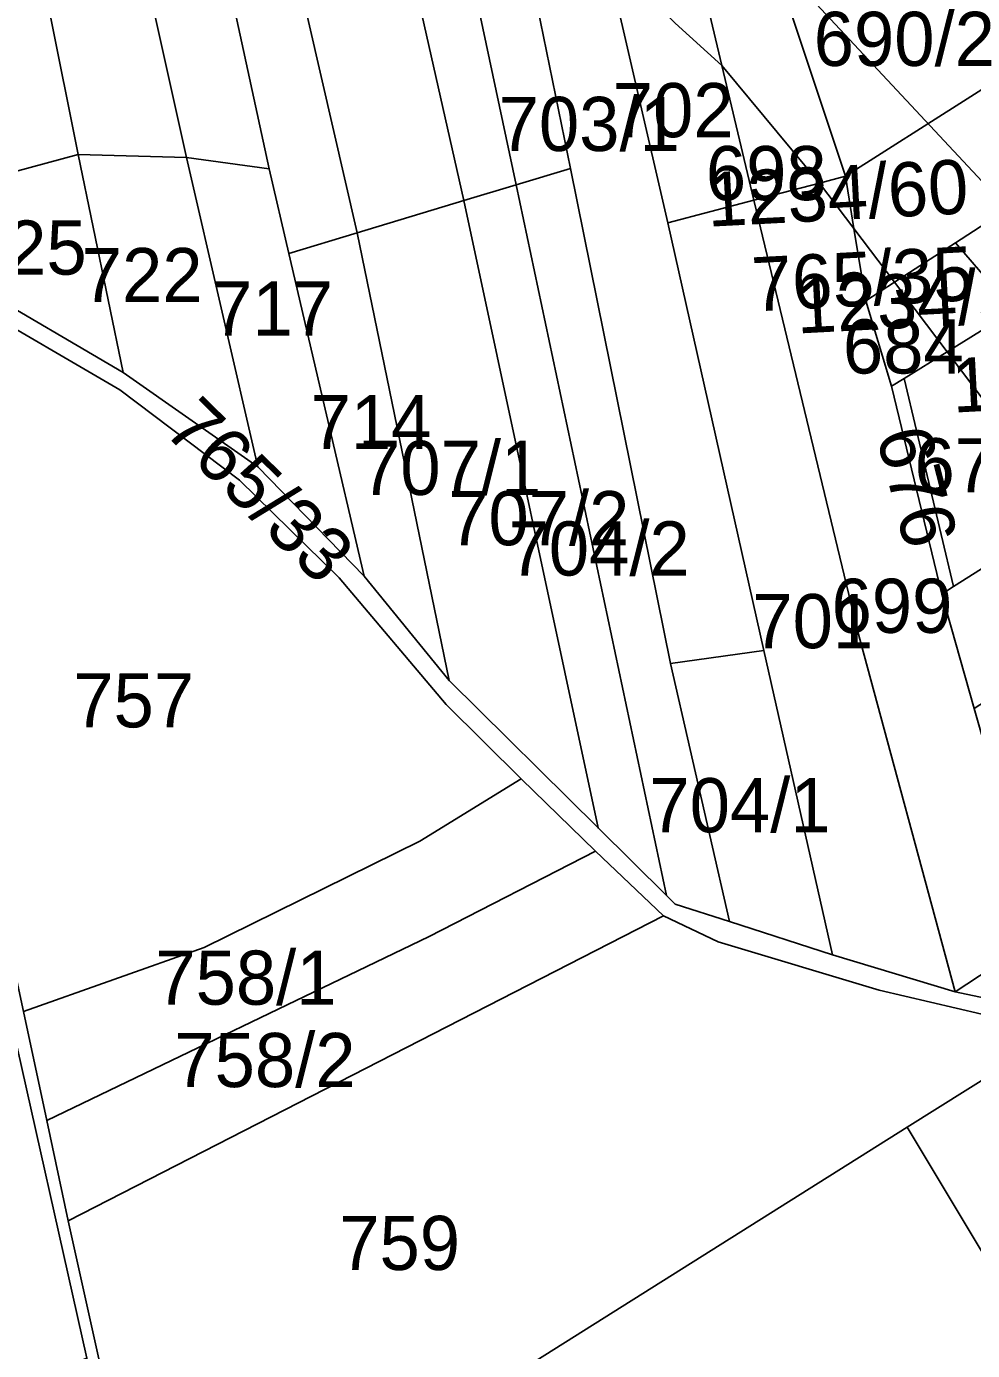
# Model space of a CAD drawing. Extents: x -623250 to -619626, y -1079612 to -1075424.
# Drawn here: x -620640.4 to -620465.7, y -1076980.5 to -1076735.9 of the extents above; entities that cross this region are included whole.
import ezdxf

# ---------------------------------------------------------------- set-up
doc = ezdxf.new("R2010")
doc.units = 0
for name, color, linetype in [('Dálnice a přivaděč', 7, 'Continuous'), ('Parcela nároku', 7, 'Continuous'), ('Parcelní číslo', 7, 'Continuous')]:
    doc.layers.add(name, color=color, linetype=linetype)

msp = doc.modelspace()

# ---------------------------------------------------------------- linework, layer by layer
at = {"layer": 'Dálnice a přivaděč'}
msp.add_lwpolyline([(-621211.3, -1075762.42), (-621042.48, -1076053.84), (-620715.11, -1076495.7), (-620421.91, -1076809.46), (-620180.94, -1077181.74)], dxfattribs=at)
at = {"layer": 'Parcela nároku'}
for points in [[(-620543.35, -1076610.93), (-620536.54, -1076607.9), (-620532.42, -1076606.06), (-620514.1, -1076675.6), (-620499.51, -1076732.52), (-620489.18, -1076763.57), (-620493.96, -1076764.83), (-620511.99, -1076743.12)], [(-620511.99, -1076743.12), (-620543.35, -1076610.93), (-620557.72, -1076617.33), (-620533.39, -1076722.78), (-620520.6, -1076735.3)], [(-620635.93, -1076647.3), (-620621.75, -1076641.56), (-620595.61, -1076762.2), (-620610.84, -1076760.14)], [(-620579.37, -1076774.02), (-620608.07, -1076649.13), (-620615.95, -1076642.08), (-620621.75, -1076641.56), (-620595.61, -1076762.2), (-620591.96, -1076777.82)], [(-620652.12, -1076653.85), (-620635.93, -1076647.3), (-620610.84, -1076760.14), (-620630.85, -1076759.56)], [(-620602.88, -1076653.77), (-620608.07, -1076649.13), (-620579.37, -1076774.02), (-620559.63, -1076768.06), (-620579.88, -1076678.27), (-620594.27, -1076664.58)], [(-620630.85, -1076759.56), (-620652.12, -1076653.85), (-620672.93, -1076659.55), (-620653.89, -1076765.75)], [(-620565.57, -1076691.88), (-620549.99, -1076765.15), (-620559.63, -1076768.06), (-620579.88, -1076678.27)], [(-620551.56, -1076705.2), (-620565.57, -1076691.88), (-620549.99, -1076765.15), (-620539.97, -1076762.12)], [(-620521.99, -1076772.19), (-620533.39, -1076722.78), (-620543.71, -1076712.67), (-620551.56, -1076705.2), (-620539.97, -1076762.12), (-620521.46, -1076853.55), (-620504.22, -1076851.17)], [(-620444.22, -1076735), (-620463.25, -1076710), (-620499.51, -1076732.52), (-620489.18, -1076763.57)], [(-620506.08, -1076768.01), (-620511.99, -1076743.12), (-620520.6, -1076735.3), (-620533.39, -1076722.78), (-620521.99, -1076772.19)], [(-620426.15, -1076723.52), (-620413.32, -1076739.86), (-620427.55, -1076749.09), (-620468.83, -1076775.85), (-620480.1, -1076783.16), (-620487.6, -1076773.24), (-620489.18, -1076763.57), (-620444.22, -1076735)], [(-620493.96, -1076764.83), (-620511.99, -1076743.12), (-620506.08, -1076768.01)], [(-620468.83, -1076775.85), (-620427.55, -1076749.09), (-620395.97, -1076793.06), (-620447.85, -1076825.87), (-620470.39, -1076795.99), (-620458.1, -1076788.35)], [(-620630.85, -1076759.56), (-620653.89, -1076765.75), (-620649.92, -1076783.79), (-620622.54, -1076799.85)], [(-620630.85, -1076759.56), (-620610.84, -1076760.14), (-620597.67, -1076817.24), (-620622.54, -1076799.85)], [(-620595.61, -1076762.2), (-620591.96, -1076777.82), (-620578.04, -1076837.42), (-620597.67, -1076817.24), (-620610.84, -1076760.14)], [(-620539.97, -1076762.12), (-620549.99, -1076765.15), (-620522.22, -1076896.42), (-620520.62, -1076898), (-620510.61, -1076901.23), (-620521.46, -1076853.55)], [(-620549.99, -1076765.15), (-620522.22, -1076896.42), (-620534.86, -1076883.93), (-620559.63, -1076768.06)], [(-620459.26, -1076883.5), (-620465.39, -1076861.89), (-620471.39, -1076840.75), (-620480.64, -1076802.35), (-620485.41, -1076786.6), (-620487.6, -1076773.24), (-620493.96, -1076764.83), (-620506.08, -1076768.01), (-620486.96, -1076847.48), (-620468.89, -1076914.21), (-620453.43, -1076904.03)], [(-620489.18, -1076763.57), (-620487.6, -1076773.24), (-620493.96, -1076764.83)], [(-620559.63, -1076768.06), (-620579.37, -1076774.02), (-620562.37, -1076856.73), (-620534.86, -1076883.93)], [(-620486.96, -1076847.48), (-620506.08, -1076768.01), (-620521.99, -1076772.19), (-620504.22, -1076851.17), (-620491.57, -1076907.38), (-620468.89, -1076914.21)], [(-620480.1, -1076783.16), (-620487.6, -1076773.24), (-620485.41, -1076786.6)], [(-620579.37, -1076774.02), (-620591.96, -1076777.82), (-620578.04, -1076837.42), (-620562.37, -1076856.73)], [(-620480.1, -1076783.16), (-620468.83, -1076775.85), (-620458.1, -1076788.35), (-620470.39, -1076795.99)], [(-620623.15, -1076803.02), (-620601.05, -1076819.72), (-620582.67, -1076837.73), (-620562.89, -1076861.13), (-620549.06, -1076874.88), (-620567.8, -1076886.37), (-620607.58, -1076906.02), (-620640.94, -1076917.83), (-620670.91, -1076778.68), (-620669.62, -1076778.45), (-620650.89, -1076786.88)], [(-620470.39, -1076795.99), (-620480.1, -1076783.16), (-620485.41, -1076786.6), (-620480.64, -1076802.35), (-620478.32, -1076800.91)], [(-620478.32, -1076800.91), (-620470.39, -1076795.99), (-620447.85, -1076825.87), (-620469.2, -1076839.37)], [(-620480.64, -1076802.35), (-620478.32, -1076800.91), (-620469.2, -1076839.37), (-620471.39, -1076840.75)], [(-620471.39, -1076840.75), (-620469.2, -1076839.37), (-620447.85, -1076825.87), (-620435.51, -1076842.53), (-620465.39, -1076861.89)], [(-620521.46, -1076853.55), (-620504.22, -1076851.17), (-620491.57, -1076907.38), (-620510.61, -1076901.23)], [(-620607.58, -1076906.02), (-620640.94, -1076917.83), (-620636.67, -1076937.95), (-620566.06, -1076904), (-620535.32, -1076888.25), (-620549.06, -1076874.88), (-620567.8, -1076886.37)], [(-620468.89, -1076914.21), (-620453.43, -1076904.03), (-620410.62, -1076875.82), (-620409.48, -1076880.02), (-620402.02, -1076890.65), (-620445.03, -1076919.25)], [(-620566.06, -1076904), (-620535.32, -1076888.25), (-620522.79, -1076900.14), (-620632.74, -1076956.48), (-620636.67, -1076937.95)], [(-620512.67, -1076904.97), (-620482.96, -1076913.88), (-620449.74, -1076921.67), (-620477.8, -1076939.19), (-620617.09, -1077026.85), (-620632.74, -1076956.48), (-620522.79, -1076900.14)], [(-620629.28, -1076981.86), (-620643.85, -1076916.74), (-620738.29, -1076956.01), (-620832.54, -1076995.23), (-620921.02, -1077031.86), (-620904.58, -1077095.56), (-620767.08, -1077038.8)], [(-620427.21, -1076931.7), (-620396.89, -1076943.7), (-620453.59, -1076979.51), (-620477.8, -1076939.19), (-620449.74, -1076921.67)], [(-620617.09, -1077026.85), (-620477.8, -1076939.19), (-620453.59, -1076979.51), (-620607.45, -1077074.44)]]:
    msp.add_lwpolyline(points, close=True, dxfattribs=at)
for points in [[(-620445.03, -1076919.25), (-620468.89, -1076914.21), (-620491.57, -1076907.38), (-620510.61, -1076901.23), (-620520.62, -1076898), (-620522.22, -1076896.42), (-620534.86, -1076883.93), (-620562.37, -1076856.73), (-620578.04, -1076837.42), (-620597.67, -1076817.24), (-620622.54, -1076799.85), (-620649.92, -1076783.79)], [(-620650.89, -1076786.88), (-620623.15, -1076803.02), (-620601.05, -1076819.72), (-620582.67, -1076837.73), (-620562.89, -1076861.13), (-620549.06, -1076874.88), (-620535.32, -1076888.25), (-620522.79, -1076900.14), (-620512.67, -1076904.97), (-620482.96, -1076913.88), (-620449.74, -1076921.67)], [(-620564.8, -1077306.77), (-620573.82, -1077257.79), (-620578.2, -1077237.62), (-620588.31, -1077189.72), (-620593.55, -1077165.29), (-620597.96, -1077153.14), (-620599.73, -1077148.14), (-620603.79, -1077103.85), (-620607.96, -1077083.92), (-620610.74, -1077070.63), (-620615.34, -1077048.34), (-620618.82, -1077032.03), (-620624.13, -1077006.64), (-620629.28, -1076981.86), (-620643.85, -1076916.74)], [(-620640.94, -1076917.83), (-620636.67, -1076937.95), (-620632.74, -1076956.48), (-620617.09, -1077026.85), (-620607.45, -1077074.44), (-620600.78, -1077101.61), (-620599.35, -1077114.69), (-620595.04, -1077151.27), (-620591.05, -1077163.8), (-620588.33, -1077176.95), (-620585.6, -1077190.18), (-620579.59, -1077219.23), (-620577.16, -1077230.36), (-620574.34, -1077243.71), (-620571.27, -1077258.42), (-620568.57, -1077271.31), (-620559.44, -1077321.56)]]:
    msp.add_lwpolyline(points, dxfattribs=at)

# ---------------------------------------------------------------- texts
at = {"layer": 'Parcelní číslo'}
for s, p in [('690/2', (-620495.03, -1076743.21)), ('702', (-620532.14, -1076756.37)), ('703/1', (-620553.22, -1076758.92)), ('698', (-620514.95, -1076768)), ('725', (-620651.61, -1076781.75)), ('722', (-620630.21, -1076786.83)), ('717', (-620606.12, -1076793.01)), ('684', (-620489.64, -1076800.01)), ('714', (-620587.95, -1076813.98)), ('707/1', (-620578.81, -1076822.44)), ('678', (-620476.42, -1076821.96)), ('707/2', (-620562.54, -1076831.73)), ('704/2', (-620551.39, -1076837.32)), ('699', (-620491.74, -1076847.91)), ('701', (-620506.36, -1076850.74)), ('757', (-620631.78, -1076865.37)), ('704/1', (-620525.37, -1076884.74)), ('758/1', (-620616.62, -1076916.59)), ('758/2', (-620613.11, -1076931.8)), ('759', (-620582.66, -1076965.58))]:
    msp.add_text(s, height=10, dxfattribs=at).set_placement(p)
for s, rotation, p in [('1234/60', 2.9794, (-620514.53, -1076772.91)), ('765/35', 2.9794, (-620506.22, -1076788.57)), ('1234/59', 2.9794, (-620498.04, -1076792.63)), ('1234/58', 2.9794, (-620469.28, -1076807.24)), ('765/33', 315.5423, (-620615.37, -1076810.76)), ('676', 284.4338, (-620483.54, -1076811.28))]:
    msp.add_text(s, height=10, rotation=rotation, dxfattribs=at).set_placement(p)

doc.saveas('drawing.dxf')
